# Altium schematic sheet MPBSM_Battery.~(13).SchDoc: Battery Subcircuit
size A3; Date: Not shown in title block; ApprovedBy: Not shown in title block; CheckedBy: Not shown in title block; Author: Not shown in title block; CompanyName: Not shown in title block; DrawnBy: Not shown in title block; Engineer: Not shown in title block; Organization: Not shown in title block; Address1: Not shown in title block; Address2: Not shown in title block; Address3: Not shown in title block; Address4: Not shown in title block; DocumentNumber: 3; Revision: Use project parameter SCH_Rev; SheetNumber: 3; SheetTotal: 12; PageSetup: Record=PageOptions¦CenterHorizontal=True¦CenterVertical=True¦PrintScale=0.69¦XCorrection=1.00¦YCorrection=1.00¦PrintKind=0¦BorderSize=5000000¦LeftOffset=0¦BottomOffset=0¦Orientation=2¦PaperLength=1000¦PaperWidth=1000¦Scale=100¦PaperSource=15¦PrintQuality=600¦MediaType=1¦DitherType=10¦PaperKind=Letter¦PrintScaleMode=1
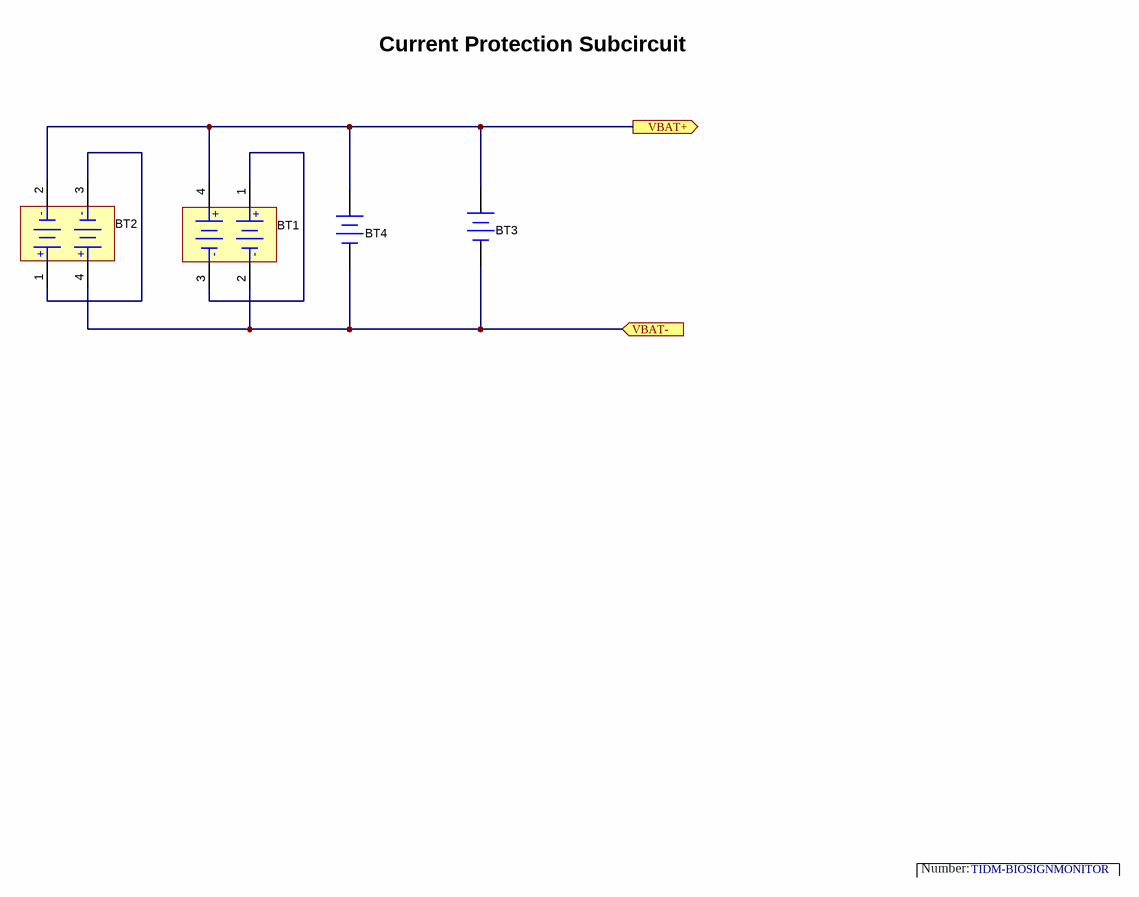
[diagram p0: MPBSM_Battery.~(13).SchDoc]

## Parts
BT1  1012  [Keystone_1012]  (value not drawn)
BT2  1012  [Keystone_1012]  (value not drawn)
BT3  XXXXXX  [Flat_Battery]  (value not drawn)
BT4  XXXXXX  [Flat_Battery]  (value not drawn)

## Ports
VBAT+ (out), VBAT- (in)

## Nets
VBAT+: BT1.4(+) BT2.2(-) BT3.1(+) BT4.1(+) ; port VBAT+
VBAT-: BT1.2(-) BT2.4(+) BT3.2(-) BT4.2(-) ; port VBAT-
NetBT1_1: BT1.1(+) BT1.3(-)
NetBT2_1: BT2.1(+) BT2.3(-)

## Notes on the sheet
- Current Protection Subcircuit
- Number:
- TIDM-BIOSIGNMONITOR

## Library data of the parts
BT1 BT2 = 1012: Battery holder for 2AA, SMD; Manufacturer: Keystone; SymbolCreator: a0411947
BT3 = Battery: Battery, Lithium Polymer, 3V, 25mAh; Manufacturer: Solicore; U/M: EA; Value: 3 Volts; TaMax_C: 60° C; TaMin_C: -10° C; Value1: 10mAh to 28mAh; Value2: Ultra-thin: 0.37mm – 0.45mm; SymbolCreator: a0272897
BT4 = Battery: Battery, Lithium Polymer, 3V, 25mAh; Manufacturer: Solicore; U/M: EA; Value: 3 Volts; Capacity: 10mAh to 28mAh; TaMax_C: 60° C; TaMin_C: -10° C; Value2: Ultra-thin: 0.37mm – 0.45mm; SymbolCreator: a0272897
